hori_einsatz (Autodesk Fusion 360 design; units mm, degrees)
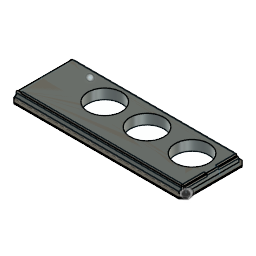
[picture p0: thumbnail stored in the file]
part number: 2025-11-18-11-09-15-142
sketch "Skizze1" plane through (0, 0, 0) normal (0, 0, 1) x axis (1, 0, 0)
  line L1 (146, 0) -> (0, 0)
  line L2 (146, 49) -> (146, 0)
  line L3 (0, 49) -> (146, 49)
  line L4 (0, 0) -> (0, 49)
  point P1 (0, 0)
  point P2 (0, 0)
  point P6 (0, 0)
  point P3 (146, 0)
  point P4 (146, 49)
  coincident P1 P2
  horizontal L1
  perpendicular L1 L2
  perpendicular L2 L3
  coincident P1 P6
  perpendicular L1 L4
  dimension "d1" distance P2 P3 = 146
  dimension "d2" distance P3 P4 = 49
extrude "Extrusion1" new body sketch "Skizze1" along normal blind 7
sketch "Skizze2" plane through (0, 0, 0) normal (0, 0, -1) x axis (1, 0, 0)
  line L1 (0, -49) -> (0, 0)
  line L2 (146, -49) -> (0, -49)
  line L3 (146, 0) -> (146, -49)
  line L4 (0, 0) -> (146, 0)
  line L5 (0, 4) -> (0, 0)
  line L6 (146, 4) -> (0, 4)
  line L7 (146, 0) -> (146, 4)
  line L8 (-4, 0) -> (0, 0)
  line L9 (-4, -49) -> (0, -49)
  line L10 (-4, -49) -> (-4, 0)
  line L11 (0, -53) -> (0, -49)
  line L12 (146, -53) -> (146, -49)
  line L13 (0, -53) -> (146, -53)
  line L14 (150, -49) -> (146, -49)
  line L15 (150, 0) -> (150, -49)
  line L16 (146, 0) -> (150, 0)
  line L17 (-4, -49) -> (0, -53)
  line L18 (-4, 0) -> (0, 4)
  line L19 (150, -49) -> (146, -53)
  line L20 (146, 4) -> (150, 0)
  point P2 (0, 0)
  point P6 (0, 0)
  point P5 (146, 0)
  point P9 (146, 0)
  point P3 (0, -49)
  point P11 (0, -49)
  point P4 (146, -49)
  point P14 (146, -49)
  point P12 (-4, -49)
  point P13 (0, -53)
  point P15 (146, -53)
  point P16 (150, -49)
  coincident P2 P6
  perpendicular L4 L5
  perpendicular L5 L6
  coincident P5 P9
  perpendicular L4 L7
  perpendicular L5 L8
  coincident P3 P11
  perpendicular L1 L9
  perpendicular L9 L11
  coincident P4 P14
  perpendicular L2 L12
  perpendicular L12 L14
  perpendicular L14 L15
  perpendicular L7 L16
  perpendicular L17 L18
  dimension "d5" distance P11 P12 = 4
  dimension "d6" distance P11 P13 = 4
  dimension "d7" distance P14 P15 = 4
  dimension "d8" distance P14 P16 = 4
extrude "Extrusion2" add sketch "Skizze2" along normal blind 2
fillet "Abrundung1" radius 1
fillet "Abrundung2" radius 1
fillet "Abrundung3" radius 1
fillet "Abrundung4" radius 1
fillet "Abrundung5" radius 1
fillet "Abrundung6" radius 1
fillet "Abrundung7" radius 1
sketch "Skizze3" plane through (0, 0, 0) normal (0, 0, 1) x axis (-1, 0, 0)
  line L1 (-145.5858, 4) -> (-0.4142, 4)
  line L2 (-149.7071, 0.2929) -> (-146.2929, 3.7071)
  line L3 (-150, -48.5858) -> (-150, -0.4142)
  line L4 (-146, -53) -> (-149.7071, -49.2929)
  line L5 (0, -53) -> (-146, -53)
  line L6 (4, -49) -> (0, -53)
  line L7 (4, 0) -> (4, -49)
  line L8 (0.2929, 3.7071) -> (4, 0)
  line L9 (-146, -1) -> (-146, -48)
  line L10 (0, 0) -> (-145, 0)
  line L11 (0, -48) -> (0, 0)
  line L12 (-145, -49) -> (-1, -49)
  line L13 (-3, 0) -> (-2.5, 0)
  line L14 (-3.01, 0) -> (-2.75, 0.1)
  line L15 (-2.5, 0) -> (-2.75, 0.1)
  arc A1 centre (-0.4142, 3) radius 1 clockwise from (-0.4142, 4) to (0.2929, 3.7071)
  arc A2 centre (-145.5858, 3) radius 1 clockwise from (-146.2929, 3.7071) to (-145.5858, 4)
  arc A3 centre (-149, -0.4142) radius 1 clockwise from (-150, -0.4142) to (-149.7071, 0.2929)
  arc A4 centre (-149, -48.5858) radius 1 clockwise from (-149.7071, -49.2929) to (-150, -48.5858)
  arc A5 centre (-145, -1) radius 1 clockwise from (-146, -1) to (-145, 0)
  arc A6 centre (-1, -48) radius 1 clockwise from (0, -48) to (-1, -49)
  arc A7 centre (-145, -48) radius 1 clockwise from (-145, -49) to (-146, -48)
  point P28 (-2.5, 0)
  point P29 (-3, 0)
  point P31 (-3.01, 0)
  coincident L10 P28
  coincident L10 P29
  coincident L10 P31
extrude "Extrusion3" add sketch "Skizze3" profile of L10 L13 L14 L15 along normal blind 4
sketch "Skizze4" plane through (0, 0, 0) normal (0, 0, 1) x axis (-1, 0, 0)
  line L1 (-2.5, 0) -> (-2.75, 0.1)
  line L2 (0, 0) -> (-2.5, 0)
  line L3 (0, -48) -> (0, 0)
  line L4 (-145, -49) -> (-1, -49)
  line L5 (-146, -1) -> (-146, -48)
  line L6 (-3.01, 0) -> (-145, 0)
  line L7 (-2.75, 0.1) -> (-3.01, 0)
  line L8 (-145.5858, 4) -> (-0.4142, 4)
  line L9 (-149.7071, 0.2929) -> (-146.2929, 3.7071)
  line L10 (-150, -48.5858) -> (-150, -0.4142)
  line L11 (-146, -53) -> (-149.7071, -49.2929)
  line L12 (0, -53) -> (-146, -53)
  line L13 (4, -49) -> (0, -53)
  line L14 (4, 0) -> (4, -49)
  line L15 (0.2929, 3.7071) -> (4, 0)
  line L16 (-134.5, 0) -> (-133.5, 0)
  line L17 (-134, 0.15) -> (-133.5, 0)
  line L18 (-134.5, 0) -> (-134, 0.15)
  arc A1 centre (-1, -48) radius 1 clockwise from (0, -48) to (-1, -49)
  arc A2 centre (-145, -48) radius 1 clockwise from (-145, -49) to (-146, -48)
  arc A3 centre (-145, -1) radius 1 clockwise from (-146, -1) to (-145, 0)
  arc A4 centre (-0.4142, 3) radius 1 clockwise from (-0.4142, 4) to (0.2929, 3.7071)
  arc A5 centre (-145.5858, 3) radius 1 clockwise from (-146.2929, 3.7071) to (-145.5858, 4)
  arc A6 centre (-149, -0.4142) radius 1 clockwise from (-150, -0.4142) to (-149.7071, 0.2929)
  arc A7 centre (-149, -48.5858) radius 1 clockwise from (-149.7071, -49.2929) to (-150, -48.5858)
  point P31 (-133.5, 0)
  point P32 (-134.5, 0)
  coincident L6 P31
  coincident L6 P32
extrude "Extrusion4" add sketch "Skizze4" profile of L6 L16 L17 L18 along normal blind 4
sketch "Skizze5" plane through (0, 0, 0) normal (0, 0, 1) x axis (-1, 0, 0)
  line L1 (-145.5858, 4) -> (-0.4142, 4)
  line L2 (-149.7071, 0.2929) -> (-146.2929, 3.7071)
  line L3 (-150, -48.5858) -> (-150, -0.4142)
  line L4 (-146, -53) -> (-149.7071, -49.2929)
  line L5 (0, -53) -> (-146, -53)
  line L6 (4, -49) -> (0, -53)
  line L7 (4, 0) -> (4, -49)
  line L8 (0.2929, 3.7071) -> (4, 0)
  line L9 (-134, 0.15) -> (-134.5, 0)
  line L10 (-133.5, 0) -> (-134, 0.15)
  line L11 (-3.01, 0) -> (-133.5, 0)
  line L12 (-2.75, 0.1) -> (-3.01, 0)
  line L13 (-2.5, 0) -> (-2.75, 0.1)
  line L14 (0, 0) -> (-2.5, 0)
  line L15 (0, -48) -> (0, 0)
  line L16 (-145, -49) -> (-1, -49)
  line L17 (-146, -1) -> (-146, -48)
  line L18 (-134.5, 0) -> (-145, 0)
  line L19 (-65, 0) -> (-64, 0)
  line L20 (-64.5, 0.2) -> (-64, 0)
  line L21 (-65, 0) -> (-64.5, 0.2)
  arc A1 centre (-0.4142, 3) radius 1 clockwise from (-0.4142, 4) to (0.2929, 3.7071)
  arc A2 centre (-145.5858, 3) radius 1 clockwise from (-146.2929, 3.7071) to (-145.5858, 4)
  arc A3 centre (-149, -0.4142) radius 1 clockwise from (-150, -0.4142) to (-149.7071, 0.2929)
  arc A4 centre (-149, -48.5858) radius 1 clockwise from (-149.7071, -49.2929) to (-150, -48.5858)
  arc A5 centre (-1, -48) radius 1 clockwise from (0, -48) to (-1, -49)
  arc A6 centre (-145, -48) radius 1 clockwise from (-145, -49) to (-146, -48)
  arc A7 centre (-145, -1) radius 1 clockwise from (-146, -1) to (-145, 0)
  point P34 (-64, 0)
  point P35 (-65, 0)
  coincident L11 P34
  coincident L11 P35
extrude "Extrusion5" add sketch "Skizze5" profile of L11 L19 L20 L21 along normal blind 4
fillet "Abrundung8" radius 0.2
fillet "Abrundung9" radius 0.2
fillet "Abrundung10" radius 0.2
sketch "Skizze6" plane through (0, 49, 0) normal (0, 1, 0) x axis (-1, 0, 0)
  line L1 (-145, 0) -> (-145, 6)
  line L2 (-1, 0) -> (-145, 0)
  line L3 (-1, 6) -> (-1, 0)
  line L4 (-145, 6) -> (-1, 6)
  line L5 (-139, 0) -> (-140, 0)
  point P6 (-140, 0)
  point P7 (-139, 0)
  coincident L2 P6
  coincident L2 P7
sketch "Skizze7" plane through (0, 0, 0) normal (0, 0, 1) x axis (-1, 0, 0)
  line L1 (-64.5, 0.2) -> (-65, 0)
  line L2 (-64, 0) -> (-64.5, 0.2)
  line L3 (-3.01, 0) -> (-64, 0)
  line L4 (-2.75, 0.1) -> (-3.01, 0)
  line L5 (-2.5, 0) -> (-2.75, 0.1)
  line L6 (0, 0) -> (-2.5, 0)
  line L7 (0, -48) -> (0, 0)
  line L8 (-145, -49) -> (-1, -49)
  line L9 (-146, -1) -> (-146, -48)
  line L10 (-134.5, 0) -> (-145, 0)
  line L11 (-134, 0.15) -> (-134.5, 0)
  line L12 (-133.5, 0) -> (-134, 0.15)
  line L13 (-65, 0) -> (-133.5, 0)
  line L14 (-145.5858, 4) -> (-0.4142, 4)
  line L15 (-149.7071, 0.2929) -> (-146.2929, 3.7071)
  line L16 (-150, -48.5858) -> (-150, -0.4142)
  line L17 (-146, -53) -> (-149.7071, -49.2929)
  line L18 (0, -53) -> (-146, -53)
  line L19 (4, -49) -> (0, -53)
  line L20 (4, 0) -> (4, -49)
  line L21 (0.2929, 3.7071) -> (4, 0)
  line L22 (-139.5, -49.2) -> (-139, -49)
  line L23 (-140, -49) -> (-139.5, -49.2)
  arc A1 centre (-1, -48) radius 1 clockwise from (0, -48) to (-1, -49)
  arc A2 centre (-145, -48) radius 1 clockwise from (-145, -49) to (-146, -48)
  arc A3 centre (-145, -1) radius 1 clockwise from (-146, -1) to (-145, 0)
  arc A4 centre (-0.4142, 3) radius 1 clockwise from (-0.4142, 4) to (0.2929, 3.7071)
  arc A5 centre (-145.5858, 3) radius 1 clockwise from (-146.2929, 3.7071) to (-145.5858, 4)
  arc A6 centre (-149, -0.4142) radius 1 clockwise from (-150, -0.4142) to (-149.7071, 0.2929)
  arc A7 centre (-149, -48.5858) radius 1 clockwise from (-149.7071, -49.2929) to (-150, -48.5858)
  point P37 (-139, -49)
  point P39 (-140, -49)
  coincident L8 P37
  coincident L8 P39
extrude "Extrusion6" add sketch "Skizze7" profile of L8 L22 L23 along normal blind 4
sketch "Skizze8" plane through (0, 0, 0) normal (0, 0, 1) x axis (-1, 0, 0)
  line L1 (-140, -49) -> (-139.5, -49.2)
  line L2 (-145, -49) -> (-140, -49)
  line L3 (-146, -1) -> (-146, -48)
  line L4 (-134.5, 0) -> (-145, 0)
  line L5 (-134, 0.15) -> (-134.5, 0)
  line L6 (-133.5, 0) -> (-134, 0.15)
  line L7 (-65, 0) -> (-133.5, 0)
  line L8 (-64.5, 0.2) -> (-65, 0)
  line L9 (-64, 0) -> (-64.5, 0.2)
  line L10 (-3.01, 0) -> (-64, 0)
  line L11 (-2.75, 0.1) -> (-3.01, 0)
  line L12 (-2.5, 0) -> (-2.75, 0.1)
  line L13 (0, 0) -> (-2.5, 0)
  line L14 (0, -48) -> (0, 0)
  line L15 (-139, -49) -> (-1, -49)
  line L16 (-139.5, -49.2) -> (-139, -49)
  line L17 (-145.5858, 4) -> (-0.4142, 4)
  line L18 (-149.7071, 0.2929) -> (-146.2929, 3.7071)
  line L19 (-150, -48.5858) -> (-150, -0.4142)
  line L20 (-146, -53) -> (-149.7071, -49.2929)
  line L21 (0, -53) -> (-146, -53)
  line L22 (4, -49) -> (0, -53)
  line L23 (4, 0) -> (4, -49)
  line L24 (0.2929, 3.7071) -> (4, 0)
  line L25 (-94.5, -49) -> (-95.5, -49)
  line L26 (-95, -49.2) -> (-95.5, -49)
  line L27 (-94.5, -49) -> (-95, -49.2)
  arc A1 centre (-145, -48) radius 1 clockwise from (-145, -49) to (-146, -48)
  arc A2 centre (-145, -1) radius 1 clockwise from (-146, -1) to (-145, 0)
  arc A3 centre (-1, -48) radius 1 clockwise from (0, -48) to (-1, -49)
  arc A4 centre (-0.4142, 3) radius 1 clockwise from (-0.4142, 4) to (0.2929, 3.7071)
  arc A5 centre (-145.5858, 3) radius 1 clockwise from (-146.2929, 3.7071) to (-145.5858, 4)
  arc A6 centre (-149, -0.4142) radius 1 clockwise from (-150, -0.4142) to (-149.7071, 0.2929)
  arc A7 centre (-149, -48.5858) radius 1 clockwise from (-149.7071, -49.2929) to (-150, -48.5858)
  point P40 (-95.5, -49)
  point P41 (-94.5, -49)
  coincident L15 P40
  coincident L15 P41
extrude "Extrusion7" add sketch "Skizze8" profile of L15 L25 L26 L27 along normal blind 4
sketch "Skizze9" plane through (0, 49, 0) normal (0, 1, 0) x axis (-1, 0, 0)
  line L1 (-14.5, 0) -> (-15.5, 0)
sketch "Skizze10" plane through (0, 0, 0) normal (0, 0, 1) x axis (-1, 0, 0)
  line L1 (-145.5858, 4) -> (-0.4142, 4)
  line L2 (-149.7071, 0.2929) -> (-146.2929, 3.7071)
  line L3 (-150, -48.5858) -> (-150, -0.4142)
  line L4 (-146, -53) -> (-149.7071, -49.2929)
  line L5 (0, -53) -> (-146, -53)
  line L6 (4, -49) -> (0, -53)
  line L7 (4, 0) -> (4, -49)
  line L8 (0.2929, 3.7071) -> (4, 0)
  line L9 (-95, -49.2) -> (-94.5, -49)
  line L10 (-95.5, -49) -> (-95, -49.2)
  line L11 (-139, -49) -> (-95.5, -49)
  line L12 (-139.5, -49.2) -> (-139, -49)
  line L13 (-140, -49) -> (-139.5, -49.2)
  line L14 (-145, -49) -> (-140, -49)
  line L15 (-146, -1) -> (-146, -48)
  line L16 (-134.5, 0) -> (-145, 0)
  line L17 (-134, 0.15) -> (-134.5, 0)
  line L18 (-133.5, 0) -> (-134, 0.15)
  line L19 (-65, 0) -> (-133.5, 0)
  line L20 (-64.5, 0.2) -> (-65, 0)
  line L21 (-64, 0) -> (-64.5, 0.2)
  line L22 (-3.01, 0) -> (-64, 0)
  line L23 (-2.75, 0.1) -> (-3.01, 0)
  line L24 (-2.5, 0) -> (-2.75, 0.1)
  line L25 (0, 0) -> (-2.5, 0)
  line L26 (0, -48) -> (0, 0)
  line L27 (-94.5, -49) -> (-1, -49)
  line L28 (-15, -49.3) -> (-15.5, -49)
  line L29 (-14.5, -49) -> (-15, -49.3)
  arc A1 centre (-0.4142, 3) radius 1 clockwise from (-0.4142, 4) to (0.2929, 3.7071)
  arc A2 centre (-145.5858, 3) radius 1 clockwise from (-146.2929, 3.7071) to (-145.5858, 4)
  arc A3 centre (-149, -0.4142) radius 1 clockwise from (-150, -0.4142) to (-149.7071, 0.2929)
  arc A4 centre (-149, -48.5858) radius 1 clockwise from (-149.7071, -49.2929) to (-150, -48.5858)
  arc A5 centre (-145, -48) radius 1 clockwise from (-145, -49) to (-146, -48)
  arc A6 centre (-145, -1) radius 1 clockwise from (-146, -1) to (-145, 0)
  arc A7 centre (-1, -48) radius 1 clockwise from (0, -48) to (-1, -49)
  point P43 (-15.5, -49)
  point P44 (-15.5, -49)
  point P46 (-14.5, -49)
  coincident P43 P44
  coincident L27 P46
extrude "Extrusion8" add sketch "Skizze10" profile of L27 L28 L29 along normal blind 4
sketch "Skizze11" plane through (0, 0, 7) normal (0, 0, 1) x axis (-1, 0, 0)
  line L1 (-145, -48) -> (-145, -1)
  line L2 (-1, -48) -> (-145, -48)
  line L3 (-1, -1) -> (-1, -48)
  line L4 (-145, -1) -> (-1, -1)
  line L5 (-145, -20) -> (-145, -30)
  line L6 (-148, -30) -> (-145, -30)
  line L7 (-148, -20) -> (-148, -30)
  line L8 (-145, -20) -> (-148, -20)
  line L9 (-146, -20) -> (-146, -30)
  point P6 (-145, -30)
  point P10 (-146, -30)
  point P11 (-146, -20)
  point P7 (-145, -20)
  coincident L1 P6
  perpendicular L5 L6
  perpendicular L6 L7
  coincident L6 P10
  coincident L8 P11
  perpendicular L8 L9
  dimension "d43" distance P6 P7 = 10
extrude "Extrusion9" add sketch "Skizze11" profile of L1 L5 L6 L8 L9 against normal blind 1.5
sketch "Skizze12" plane through (0, 0, 7) normal (0, 0, 1) x axis (-1, 0, 0)
  line L1 (-145, -48) -> (-145, -30)
  line L2 (-1, -48) -> (-145, -48)
  line L3 (-1, -1) -> (-1, -48)
  line L4 (-145, -1) -> (-1, -1)
  line L5 (-145, -20) -> (-145, -1)
  line L6 (-146, -20) -> (-145, -20)
  line L7 (-146, -30) -> (-146, -20)
  line L8 (-145, -30) -> (-146, -30)
  line L9 (-1, -20) -> (-1, -30)
  line L10 (0, -20) -> (-1, -20)
  line L11 (0, -30) -> (0, -20)
  line L12 (-1, -30) -> (0, -30)
  point P10 (-1, -30)
  point P11 (-1, -20)
  coincident L3 P10
  coincident L3 P11
  perpendicular L9 L10
  perpendicular L10 L11
  perpendicular L9 L12
extrude "Extrusion10" add sketch "Skizze12" profile of L3 L9 L10 L11 L12 against normal blind 2
sketch "Skizze13" plane through (0, 0, 7) normal (0, 0, 1) x axis (-1, 0, 0)
  line L1 (-145, -48) -> (-145, -30)
  line L2 (-1, -48) -> (-145, -48)
  line L3 (-1, -30) -> (-1, -48)
  line L4 (0, -30) -> (-1, -30)
  line L5 (0, -20) -> (0, -30)
  line L6 (-1, -20) -> (0, -20)
  line L7 (-1, -1) -> (-1, -20)
  line L8 (-145, -1) -> (-1, -1)
  line L9 (-145, -20) -> (-145, -1)
  line L10 (-146, -20) -> (-145, -20)
  line L11 (-146, -30) -> (-146, -20)
  line L12 (-145, -30) -> (-146, -30)
sketch "Skizze14" plane through (0, 0, 7) normal (0, 0, 1) x axis (-1, 0, 0)
  line L1 (2, -30) -> (0, -30)
  line L2 (2, -20) -> (0, -20)
  line L3 (2, -30) -> (2, -20)
  line L4 (0, -20) -> (0, -30)
  point P2 (0, -30)
  point P3 (0, -30)
  point P5 (0, -20)
  point P6 (0, -20)
  point P4 (2, -30)
  point P7 (2, -20)
  coincident P2 P3
  coincident P5 P6
  perpendicular L1 L3
  perpendicular L2 L4
  dimension "d48" distance P3 P4 = 2
  dimension "d49" distance P6 P7 = 2
extrude "Extrusion11" add sketch "Skizze14" against normal blind 5
sketch "Skizze15" plane through (0, 0, 7) normal (0, 0, 1) x axis (-1, 0, 0)
  line L1 (-149, -20) -> (-146, -20)
  line L2 (-149, -30) -> (-149, -20)
  line L3 (-146, -30) -> (-149, -30)
  line L4 (-146, -20) -> (-146, -30)
  horizontal L1
  perpendicular L1 L2
  perpendicular L2 L3
  perpendicular L1 L4
extrude "Extrusion12" add sketch "Skizze15" against normal blind 5
sketch "Skizze16" plane through (0, 0, 2) normal (0, 0, -1) x axis (1, 0, 0)
  line L1 (146, -30) -> (146, -20)
  line L2 (149, -30) -> (146, -30)
  line L3 (149, -20) -> (149, -30)
  line L4 (146, -20) -> (149, -20)
sketch "Skizze17" plane through (0, 30, 0) normal (0, 1, 0) x axis (-1, 0, 0)
  line L1 (-149, 7) -> (-145, 7)
  line L2 (-149, 2) -> (-149, 7)
  line L3 (-146, 2) -> (-149, 2)
  line L4 (-146, 6) -> (-146, 2)
  arc A1 centre (-145, 6) radius 1 clockwise from (-146, 6) to (-145, 7)
extrude "Extrusion13" add of existing geometry blind 1.5
extrude "Extrusion14" add sketch "Skizze16" along normal blind 1.5
sketch "Skizze18" plane through (0, 30, 0) normal (0, 1, 0) x axis (-1, 0, 0)
  line L1 (-149, 7) -> (-145, 7)
  line L2 (-149, 0.5) -> (-149, 7)
  line L3 (-146, 0.5) -> (-149, 0.5)
  line L4 (-146, 6) -> (-146, 0.5)
  line L5 (0.5, 6) -> (0, 6)
  line L6 (1, 0.5) -> (0.5, 6)
  line L7 (2, 0.8) -> (1, 0.5)
  line L8 (2, 0.5) -> (1, 0.5)
  line L9 (0, 0.5) -> (1, 0.5)
  line L10 (0, 6) -> (0, 0.5)
  line L11 (2, 0.5) -> (2, 0.8)
  arc A1 centre (-145, 6) radius 1 clockwise from (-146, 6) to (-145, 7)
  point P12 (2, 0.5)
  point P13 (2, 0.5)
  point P14 (0, 0.5)
  point P15 (0, 0.5)
  horizontal L5
  coincident P12 P13
  coincident P14 P15
  perpendicular L5 L10
extrude "Extrusion15" cut sketch "Skizze18" profile of L5 L6 L7 L8 L9 L10 L11 against normal blind 18
fillet "Abrundung11" radius 2
sketch "Skizze19" plane through (0, 30, 0) normal (0, 1, 0) x axis (-1, 0, 0)
  line L1 (-146.5, 6) -> (-146, 6)
  line L2 (-147, 0.5) -> (-146.5, 6)
  line L3 (-148, 1) -> (-147, 0.5)
  line L4 (-148, 7) -> (-148, 1)
  line L5 (-146, 7) -> (-148, 7)
  line L6 (-146, 6) -> (-146, 7)
  line L7 (-146, 0.5) -> (-147, 0.5)
  line L8 (-146, 6) -> (-146, 0.5)
  line L9 (-147, 0.5) -> (-146.5, 6)
  line L10 (-146.5, 6) -> (-147, 0.5)
  line L11 (-146, 0.5) -> (-146, 6)
  horizontal L1
  perpendicular L1 L4
  perpendicular L4 L5
  perpendicular L1 L6
  horizontal L7
  perpendicular L1 L8
extrude "Extrusion16" cut sketch "Skizze19" profile of L1 L2 L7 L8 L9 L10 L11 against normal blind 24.5
extrude "Extrusion17" cut of existing geometry blind -1
fillet "Abrundung12" radius 1
fillet "Abrundung13" radius 1
fillet "Abrundung14" radius 1
extrude "Extrusion18" add of existing geometry blind 2
fillet "Abrundung15" radius 1
extrude "Extrusion19" add of existing geometry blind 2
extrude "Extrusion20" add of existing geometry blind 1
extrude "Extrusion21" add of existing geometry blind 3.5
extrude "Extrusion22" add of existing geometry blind 2
extrude "Extrusion23" add of existing geometry blind 2.5
fillet "Abrundung16" radius 2
move_face "Fläche verschieben1"
move_face "Fläche verschieben2"
move_face "Fläche verschieben3"
sketch "Skizze20" plane through (-2, 0, 0) normal (-1, 0, 0) x axis (0, -1, 0)
  line L1 (-48, 5) -> (0, 5)
  line L2 (-48, 0) -> (-48, 5)
  line L3 (0, 0) -> (-48, 0)
  line L4 (0, 5) -> (0, 0)
  line L5 (0, 1) -> (0, 0)
  line L6 (4, 1) -> (0, 1)
  line L7 (0, 4.5) -> (4, 1)
  point P1 (0, 0)
  point P6 (0, 0)
  point P7 (0, 1)
  point P9 (0, 4.5)
  coincident P1 P6
  coincident L4 P7
  perpendicular L5 L6
  coincident L4 P9
extrude "Extrusion24" add sketch "Skizze20" profile of L4 L6 L7 against normal blind 3
delete_face "Fläche löschen1"
delete_face "Fläche löschen2"
extrude "Extrusion25" add of existing geometry blind 129
delete_face "Fläche löschen3"
extrude "Extrusion26" add of existing geometry blind 15
fillet "Abrundung17" radius 1
sketch "Skizze21" plane through (148, 0, 0) normal (1, 0, 0) x axis (0, 1, 0)
  line L1 (30, 5) -> (48, 5)
  line L2 (30, 6) -> (30, 5)
  line L3 (20, 6) -> (30, 6)
  line L4 (20, 5) -> (20, 6)
  line L5 (1, 5) -> (20, 5)
  line L6 (1, 0) -> (1, 5)
  line L7 (48, 0) -> (1, 0)
  line L8 (48, 5) -> (48, 0)
  line L9 (2.5, 1) -> (1, 1)
  point P10 (1, 1)
  coincident L6 P10
  perpendicular L6 L9
sketch "Skizze22" plane through (0, 1, 0) normal (0, -1, 0) x axis (1, 0, 0)
  line L1 (146, 6) -> (147, 6)
  line L2 (146, 0) -> (146, 6)
  line L3 (148, 0) -> (146, 0)
  line L4 (148, 5) -> (148, 0)
  line L5 (148, 1) -> (146, 1)
  line L6 (146, 0) -> (148, 0)
  line L7 (146.9, 0.9) -> (146, 1)
  arc A1 centre (147, 5) radius 1 clockwise from (147, 6) to (148, 5)
  point P8 (146, 1)
  point P9 (148, 1)
  point P7 (148, 0)
  point P10 (148, 0)
  point P6 (146, 0)
  point P11 (146, 0)
  coincident L2 P8
  coincident L4 P9
  perpendicular L4 L5
  coincident P7 P10
  coincident P6 P11
extrude "Extrusion27" cut sketch "Skizze22" profile of L2 L3 L4 L5 L6 against normal blind 53
fillet "Abrundung18" radius 1
sketch "Skizze23" plane through (0, -2.2301, 2.5487) normal (0, -0.6585, 0.7526) x axis (1, 0, 0)
  line L1 (145, 0.3096) -> (-2, 0.3096)
  line L2 (145, 2.9633) -> (145, 0.3096)
  line L3 (-2, 2.9633) -> (145, 2.9633)
  line L4 (-2, 0.3096) -> (-2, 2.9633)
sketch "Skizze24" plane through (0, 0, 0) normal (0, -1, 0) x axis (1, 0, 0)
  line L1 (-2, 1) -> (64, 1)
  line L2 (-2, 0) -> (-2, 1)
  line L3 (64, 0) -> (-2, 0)
  line L4 (64, 1) -> (64, 0)
  line L5 (-1, 1) -> (-2, 1)
  line L6 (-2, 0) -> (-1, 0)
  line L7 (-1, 1) -> (-2, 1)
  line L8 (-1, 0) -> (-1, 1)
  line L9 (-2, 0) -> (-2, 1)
  point P3 (-2, 1)
  point P6 (-2, 1)
  point P7 (-1, 1)
  point P8 (-1, 0)
  point P4 (-2, 0)
  point P9 (-2, 0)
  coincident P3 P6
  coincident L1 P7
  coincident L3 P8
  coincident P4 P9
  perpendicular L3 L8
extrude "Extrusion28" cut sketch "Skizze24" profile of L1 L2 L3 L5 L6 L7 L8 L9 against normal blind 50
fillet "Abrundung19" radius 1
hole "Bohrung1" HoleDepth 23 HoleDiameter 30 TipAngle 118
hole "Bohrung2" HoleDepth 23 HoleDiameter 30 TipAngle 118
hole "Bohrung3" HoleDepth 23 HoleDiameter 30 TipAngle 118
extrude "Extrusion29" cut sketch "Skizze6" against normal blind 0.5
extrude "Extrusion30" cut of existing geometry blind -1
extrude "Extrusion31" add of existing geometry blind 0.5
extrude "Extrusion32" add of existing geometry blind 0.5
extrude "Extrusion33" add of existing geometry blind 0.5
extrude "Extrusion34" cut of existing geometry blind -2.5
extrude "Extrusion35" cut of existing geometry blind -4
